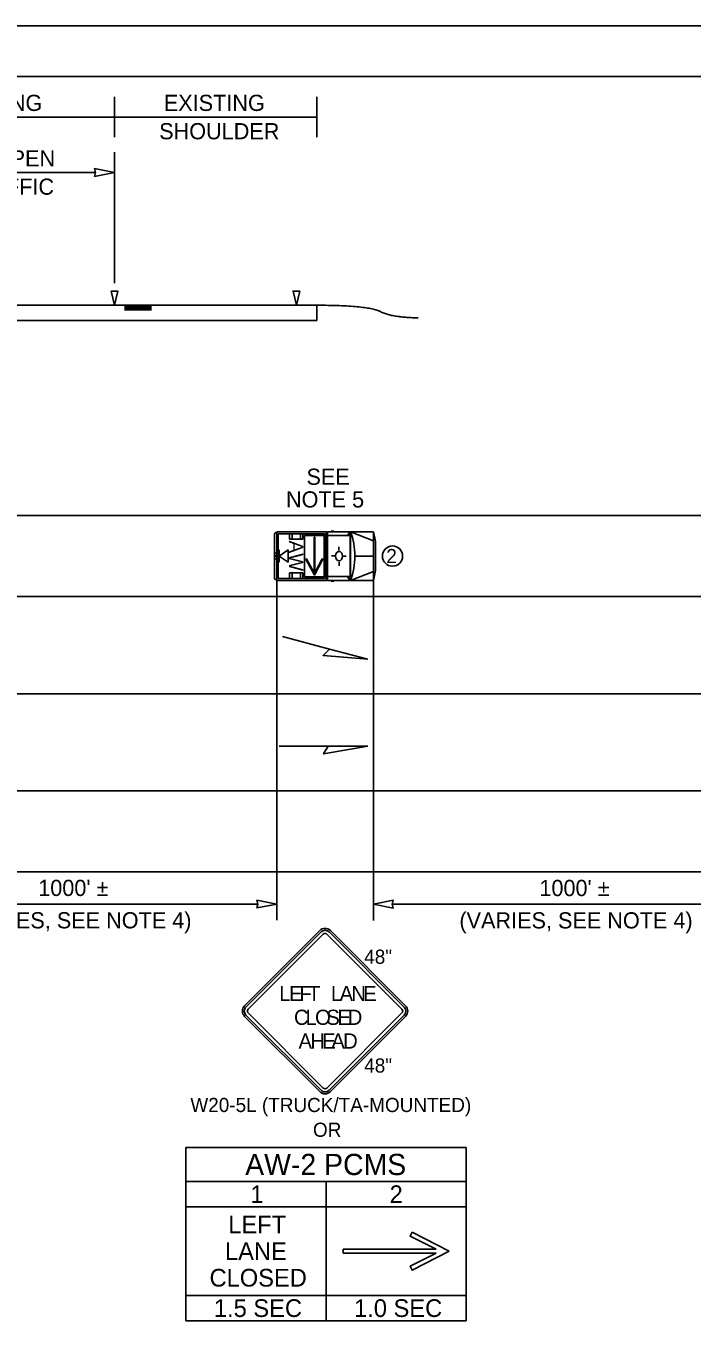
# Model space of a CAD drawing. Extents: x 0 to 17, y 0 to 11.
# Drawn here: x 8.42 to 11.71, y 4.59 to 11 of the extents above; entities that cross this region are included whole.
import ezdxf

# ---------------------------------------------------------------- set-up
doc = ezdxf.new("R2010")
doc.units = 0
for name, color, linetype in [('RD_ED_ShoulderPavedEdge', 7, 'Continuous'), ('RD_MK_LineEdgeWhite', 7, 'Continuous'), ('RD_MK_LineEdgeYellow', 7, 'Continuous'), ('RD_MK_LineLane', 7, 'Continuous'), ('SH_GI_PlotLimits', 7, 'Continuous'), ('SH_GI_SheetBorder3', 7, 'Continuous'), ('SH_TI_WZSectionCut', 7, 'Continuous'), ('TR_SN_ConstructionSigns', 7, 'Continuous'), ('TR_WZ_PortableChangeMessageSign', 7, 'Continuous'), ('TR_WZ_PortableSignMountBlk-Org', 7, 'Continuous'), ('TR_WZ_ProtectiveVehicle', 7, 'Continuous'), ('TR_WZ_TransportableAttenuator', 7, 'Continuous'), ('TR_WZ_WorkZoneDetails', 7, 'Continuous'), ('TR_WZ_WorkZoneTextCurrent', 7, 'Continuous')]:
    doc.layers.add(name, color=color, linetype=linetype)

msp = doc.modelspace()

# ---------------------------------------------------------------- linework, layer by layer
at = {"layer": 'RD_ED_ShoulderPavedEdge'}
for p, q in [((1.8283, 8.5807), (16.62, 8.5807)), ((1.8283, 6.8207), (16.62, 6.8207))]:
    msp.add_line(p, q, dxfattribs=at)
at = {"layer": 'RD_MK_LineEdgeWhite'}
msp.add_line((1.8283, 7.2207), (16.62, 7.2207), dxfattribs=at)
at = {"layer": 'RD_MK_LineEdgeYellow'}
msp.add_line((1.8283, 8.1807), (16.62, 8.1807), dxfattribs=at)
at = {"layer": 'RD_MK_LineLane'}
msp.add_line((16.62, 7.7007), (1.8283, 7.7007), dxfattribs=at)
at = {"layer": 'SH_GI_PlotLimits'}
msp.add_lwpolyline([(0, 11), (17, 11), (17, 0), (0, 0)], close=True, dxfattribs=at)
at = {"layer": 'SH_GI_SheetBorder3'}
msp.add_line((1, 10.75), (16.75, 10.75), dxfattribs=at)
at = {"layer": 'SH_TI_WZSectionCut'}
for p, q in [((8.8546, 10.45), (8.8546, 10.65)), ((9.8546, 10.45), (9.8546, 10.65)), ((7.6546, 10.55), (8.8546, 10.55)), ((8.8546, 10.55), (9.8546, 10.55)), ((8.8546, 9.7297), (8.8546, 10.376)), ((8.7609, 10.276), (7.7484, 10.276)), ((9.8546, 9.6199), (5.4546, 9.6199)), ((9.0376, 9.6143), (8.9046, 9.6143)), ((9.0376, 9.6087), (8.9046, 9.6087)), ((9.0376, 9.603), (8.9046, 9.603)), ((9.0376, 9.5978), (8.9046, 9.5978)), ((9.8546, 9.6199), (9.8546, 9.5449)), ((9.8546, 9.5449), (5.4546, 9.5449))]:
    msp.add_line(p, q, dxfattribs=at)
for points in [[(8.8546, 10.276), (8.7564, 10.2567), (8.7609, 10.276), (8.7564, 10.2953)], [(8.838, 9.6897), (8.8713, 9.6897), (8.8547, 9.6199)]]:
    msp.add_lwpolyline(points, close=True, dxfattribs=at)
msp.add_lwpolyline([(9.7713, 9.6897), (9.7379, 9.6897), (9.7546, 9.6199), (9.7713, 9.6897)], dxfattribs=at)
msp.add_open_spline([(9.8546, 9.6199), (10.1058, 9.6201), (10.2313, 9.558), (10.3568, 9.5581)], degree=2, dxfattribs=at)
at = {"layer": 'TR_SN_ConstructionSigns'}
for p, q in [((9.8694, 6.5301), (9.4982, 6.1588)), ((9.876, 6.5234), (9.5048, 6.1522)), ((9.5158, 6.1411), (9.8871, 6.5124)), ((9.9048, 6.5124), (10.276, 6.1411)), ((10.2871, 6.1522), (9.9158, 6.5234)), ((10.2937, 6.1588), (9.9224, 6.5301)), ((9.4982, 6.1058), (9.8694, 5.7345)), ((9.5048, 6.1124), (9.876, 5.7412)), ((9.8871, 5.7522), (9.5158, 6.1235)), ((10.276, 6.1235), (9.9048, 5.7522)), ((9.9158, 5.7412), (10.2871, 6.1124)), ((9.9224, 5.7345), (10.2937, 6.1058))]:
    msp.add_line(p, q, dxfattribs=at)
for centre, radius, start, end in [((9.8959, 6.5036), 0.0375, 45, 135), ((9.8959, 6.5036), 0.0281, 45, 135), ((9.8959, 6.5036), 0.0125, 45, 135), ((9.5247, 6.1323), 0.0375, 135, 225.00001), ((10.2672, 6.1323), 0.0375, 315.00001, 45.00001), ((9.5247, 6.1323), 0.0281, 135, 225.00001), ((9.5247, 6.1323), 0.0125, 135, 225.00001), ((10.2672, 6.1323), 0.0125, 315.00002, 45), ((10.2672, 6.1323), 0.0281, 315.00002, 45), ((9.8959, 5.7611), 0.0375, 225.00001, 315.00001), ((9.8959, 5.7611), 0.0281, 225.00001, 315.00002), ((9.8959, 5.7611), 0.0125, 225.00001, 315.00002)]:
    msp.add_arc(centre, radius, start, end, dxfattribs=at)
at = {"layer": 'TR_WZ_PortableChangeMessageSign'}
for p, q in [((9.2079, 5.4586), (10.5939, 5.4586)), ((9.2079, 4.6018), (9.2079, 5.4586)), ((10.5939, 4.6018), (10.5939, 5.4586)), ((10.5939, 5.2906), (9.2079, 5.2906)), ((9.9009, 4.6018), (9.9009, 5.2906)), ((9.9009, 5.1646), (9.2079, 5.1646)), ((10.5939, 5.1646), (9.9009, 5.1646)), ((10.3259, 5.0395), (10.5099, 4.9462)), ((9.9849, 4.9357), (9.9849, 4.9567)), ((9.9849, 4.9567), (10.4448, 4.9567)), ((10.4448, 4.9357), (9.9849, 4.9357)), ((9.2079, 4.7278), (9.9009, 4.7278)), ((9.9009, 4.7278), (10.5939, 4.7278)), ((10.5939, 4.6018), (9.2079, 4.6018))]:
    msp.add_line(p, q, dxfattribs=at)
for points in [[(10.4448, 4.9567), (10.3165, 5.0208), (10.3212, 5.0302), (10.3259, 5.0395)], [(10.5099, 4.9462), (10.3259, 4.8528), (10.3212, 4.8622), (10.3165, 4.8715), (10.4448, 4.9357)]]:
    msp.add_lwpolyline(points, dxfattribs=at)
at = {"layer": 'TR_WZ_PortableSignMountBlk-Org'}
msp.add_line((9.6696, 8.4107), (9.6696, 8.3507), dxfattribs=at)
msp.add_lwpolyline([(9.6696, 8.3807), (9.7127, 8.3507), (9.7127, 8.4107)], close=True, dxfattribs=at)
at = {"layer": 'TR_WZ_ProtectiveVehicle'}
for p, q in [((9.6462, 8.272), (9.6462, 8.4895)), ((9.6515, 8.4968), (9.6569, 8.4968)), ((9.6569, 8.2647), (9.6569, 8.4968)), ((9.6577, 8.5007), (9.9046, 8.5007)), ((9.6577, 8.2607), (9.6577, 8.5007)), ((9.6647, 8.2703), (9.6647, 8.4912)), ((9.6647, 8.4912), (9.8976, 8.4912)), ((9.7204, 8.4912), (9.7204, 8.4635)), ((9.7335, 8.4912), (9.7335, 8.4635)), ((9.7743, 8.4912), (9.7743, 8.4635)), ((9.7863, 8.4912), (9.7863, 8.4635)), ((9.8976, 8.2703), (9.8976, 8.4912)), ((9.9046, 8.2607), (9.9046, 8.5007)), ((9.9079, 8.2607), (9.9079, 8.5007)), ((10.1346, 8.5007), (9.9079, 8.5007)), ((10.0192, 8.4821), (9.9079, 8.4821)), ((9.9388, 8.5041), (9.9252, 8.5041)), ((10.0072, 8.4821), (10.0192, 8.5007)), ((10.0192, 8.2607), (10.0192, 8.5007)), ((10.0212, 8.2607), (10.0212, 8.5007)), ((10.1346, 8.4568), (10.0212, 8.5007)), ((10.1346, 8.2607), (10.1346, 8.5007)), ((10.1346, 8.5007), (10.1457, 8.4523)), ((9.7204, 8.4635), (9.7863, 8.4635)), ((9.9639, 8.4269), (9.9642, 8.4088)), ((10.1457, 8.3092), (10.1457, 8.4523)), ((9.6462, 8.3976), (9.6569, 8.3931)), ((9.6462, 8.3638), (9.6569, 8.3683)), ((9.6491, 8.3807), (9.654, 8.3807)), ((9.6515, 8.3773), (9.6515, 8.3841)), ((9.9277, 8.3816), (9.9456, 8.3812)), ((9.9479, 8.3811), (9.9479, 8.3811)), ((9.9648, 8.3332), (9.9648, 8.3525)), ((10.0009, 8.3806), (9.9858, 8.3806)), ((10.1346, 8.3807), (10.0435, 8.3807)), ((9.7204, 8.2979), (9.7863, 8.2979)), ((9.7204, 8.2703), (9.7204, 8.2979)), ((9.7335, 8.2703), (9.7335, 8.2979)), ((9.7743, 8.2703), (9.7743, 8.2979)), ((9.7863, 8.2703), (9.7863, 8.2979)), ((10.0192, 8.2793), (9.9079, 8.2793)), ((10.0192, 8.2607), (10.0047, 8.2793)), ((10.1346, 8.3047), (10.0212, 8.2607)), ((10.1346, 8.2607), (10.1457, 8.3092)), ((9.6515, 8.2647), (9.6569, 8.2647)), ((9.6577, 8.2607), (9.9046, 8.2607)), ((9.6647, 8.2703), (9.8976, 8.2703)), ((10.1346, 8.2607), (9.9079, 8.2607)), ((9.9388, 8.2573), (9.9252, 8.2573))]:
    msp.add_line(p, q, dxfattribs=at)
for centre, major_axis, start_param, end_param in [((9.6515, 8.4895), (0, 0.00732), 0, 1.570796), ((9.8592, 8.3808), (0, 0.2518), 4.215667, 5.208926), ((9.6515, 8.272), (0, -0.00732), 4.712389, 6.283185)]:
    msp.add_ellipse(centre, major_axis=major_axis, ratio=0.73155, start_param=start_param, end_param=end_param, dxfattribs=at)
for centre, major_axis in [((9.9648, 8.3807), (0, -0.0231)), ((9.6515, 8.3807), (0, -0.00338))]:
    msp.add_ellipse(centre, major_axis=major_axis, ratio=0.73155, dxfattribs=at)
at = {"layer": 'TR_WZ_TransportableAttenuator'}
for points in [[(9.795, 8.4825), (9.891, 8.4825), (9.891, 8.2789), (9.795, 8.2789)], [(9.8414, 8.4743), (9.8414, 8.2973), (9.8446, 8.2973), (9.8446, 8.4743)], [(9.8016, 8.3646), (9.843, 8.2871), (9.8414, 8.2973), (9.8043, 8.3669)], [(9.843, 8.2871), (9.8843, 8.3646), (9.8816, 8.3669), (9.8446, 8.2973)], [(9.843, 8.2871), (9.8446, 8.2973), (9.8414, 8.2973)]]:
    msp.add_lwpolyline(points, close=True, dxfattribs=at)
at = {"layer": 'TR_WZ_WorkZoneDetails'}
for p, q in [((9.6569, 8.2607), (9.6569, 6.5811)), ((10.1346, 8.2607), (10.1346, 6.5807)), ((9.9175, 7.9214), (9.6846, 7.9838)), ((9.9108, 7.4414), (9.6697, 7.4414)), ((9.5632, 6.6611), (7.7506, 6.6611)), ((12.0408, 6.6607), (10.2283, 6.6607))]:
    msp.add_line(p, q, dxfattribs=at)
for points in [[(10.1073, 7.8706), (9.8859, 7.89), (9.9175, 7.9214)], [(10.1073, 7.4414), (9.8885, 7.4029), (9.9108, 7.4414)], [(9.6569, 6.6611), (9.5586, 6.6803), (9.5632, 6.6611), (9.5586, 6.6418)], [(10.1346, 6.6607), (10.2328, 6.68), (10.2283, 6.6607), (10.2328, 6.6415)]]:
    msp.add_lwpolyline(points, close=True, dxfattribs=at)
msp.add_circle((10.2294, 8.3807), 0.05, dxfattribs=at)

# ---------------------------------------------------------------- texts
at = {"layer": 'SH_TI_WZSectionCut'}
for s, p in [('EXISTING', (7.9986, 10.58)), ('EXISTING', (9.0986, 10.58)), ('SHOULDER', (9.0757, 10.44))]:
    msp.add_text(s, height=0.08, rotation=360, dxfattribs=at).set_placement(p)
for s, p in [('LANE OPEN', (7.9489, 10.306)), ('TO TRAFFIC', (7.9261, 10.166))]:
    msp.add_text(s, height=0.08, dxfattribs=at).set_placement(p)
at = {"layer": 'TR_SN_ConstructionSigns'}
for s, height, p in [('48"', 0.07, (10.0895, 6.366)), ('L', 0.075, (9.669, 6.1815)), ('E', 0.075, (9.7178, 6.1815)), ('F', 0.075, (9.7688, 6.1815)), ('T', 0.075, (9.8115, 6.1815)), ('L', 0.075, (9.9248, 6.1815)), ('A', 0.075, (9.9676, 6.1815)), ('N', 0.075, (10.0261, 6.1815)), ('E', 0.075, (10.0846, 6.1815)), ('C', 0.075, (9.7422, 6.0643)), ('L', 0.075, (9.7992, 6.0643)), ('O', 0.075, (9.8464, 6.0643)), ('S', 0.075, (9.9019, 6.0643)), ('E', 0.075, (9.9567, 6.0643)), ('D', 0.075, (10.0077, 6.0643)), ('A', 0.075, (9.7647, 5.9471)), ('H', 0.075, (9.8232, 5.9471)), ('E', 0.075, (9.8817, 5.9471)), ('A', 0.075, (9.9267, 5.9471)), ('D', 0.075, (9.9852, 5.9471)), ('48"', 0.07, (10.0895, 5.8286)), ('W20-5L (TRUCK/TA-MOUNTED)', 0.07, (9.2299, 5.6336)), ('OR', 0.07, (9.836, 5.5111))]:
    msp.add_text(s, height=height, dxfattribs=at).set_placement(p)
at = {"layer": 'TR_WZ_PortableChangeMessageSign'}
for s, height, p in [('AW-2 PCMS', 0.105, (9.5011, 5.3221)), ('1', 0.0875, (9.527, 5.1838)), ('2', 0.0875, (10.215, 5.1838)), ('LEFT', 0.0875, (9.4172, 5.0337)), ('LANE', 0.0875, (9.4012, 4.9024)), ('CLOSED', 0.0875, (9.3247, 4.7712)), ('1.5 SEC', 0.0875, (9.3462, 4.621)), ('1.0 SEC', 0.0875, (10.0392, 4.621))]:
    msp.add_text(s, height=height, rotation=360, dxfattribs=at).set_placement(p)
at = {"layer": 'TR_WZ_ProtectiveVehicle'}
msp.add_text('AW', height=0.07, rotation=270, dxfattribs=at).set_placement((9.7183, 8.4574))
at = {"layer": 'TR_WZ_WorkZoneDetails'}
msp.add_text('2', height=0.07, dxfattribs=at).set_placement((10.1986, 8.3457))
at = {"layer": 'TR_WZ_WorkZoneTextCurrent'}
for s, p in [('SEE', (9.8039, 8.7327)), ('NOTE 5', (9.7026, 8.6207)), ("1000' ±", (8.4778, 6.7011)), ("1000' ±", (10.9555, 6.7007)), ('(VARIES, SEE NOTE 4)', (8.0822, 6.5411)), ('(VARIES, SEE NOTE 4)', (10.5599, 6.5407))]:
    msp.add_text(s, height=0.08, dxfattribs=at).set_placement(p)

doc.saveas('drawing.dxf')
